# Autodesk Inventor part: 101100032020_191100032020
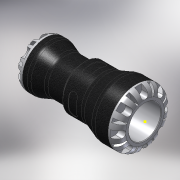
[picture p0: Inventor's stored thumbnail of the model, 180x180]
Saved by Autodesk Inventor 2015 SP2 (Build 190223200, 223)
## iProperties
Created: 2016-12
Part Number: 101100032020_191100032020
Material: PVC-Piping
Description: PLASSON REDUCING COUPLING 32X20 SERIES 1
Document SubType Name: Modeling
Designer: KIM
Mass: 145.674 g
Surface Area: 294.083 cm^2
Volume: 104.053 cm^3
Density: 1.4 g/cm^3
Appearance: Black Cast
Author: KIM
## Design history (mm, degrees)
derived "1011.ipt"
feature "Solid1::1011.ipt"
tag "TaggingFeature1"
body "Solid1"
other parameters: "d0" = 106, "d2" = 22.68, "d3" = 32, "d4" = 58, "d5" = 38.4, "d6" = 54, "d7" = 2.66667, "d8" = 41, "d10" = 25, "d11" = 18.9, "d12" = 45, "d13" = 1.66667, "d14" = 46.4, "d15" = 32.8, "d16" = 20 deg, "d17" = 20 deg, "d18" = 130 deg, "d22" = 7.84, "d25" = 7.84, "d26" = 0, "d28" = 360 deg, "d30" = 8 deg, "d31" = 0.64, "d32" = 8 deg, "d33" = 0.64, "d35" = 0, "d37" = 360 deg, "d39" = 6.4, "d42" = 6.4, "d43" = 0, "d45" = 360 deg, "d47" = 0.4, "d48" = 8 deg, "d49" = 8 deg, "d50" = 0.4, "d52" = 0, "d54" = 360 deg, "d56" = 8.2, "d57" = 11.6, "d58" = 0.5, "d60" = 6.96, "d61" = 8, "d62" = 12.96, "d63" = 0, "d66" = 0, "d68" = 360 deg, "d75" = 5.4501, "d77" = 45.24, "d78" = 0.58, "d_" = 32, "E_" = 58, "H_" = 106, "l_" = 54, "E1" = 41, "l1" = 45, "Plasson" = 1, "d20" = 8, "d21" = 9.8, "d23" = 58, "d24" = 38.4, "d40" = 41, "d41" = 25, "d59" = 10.90021
